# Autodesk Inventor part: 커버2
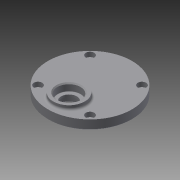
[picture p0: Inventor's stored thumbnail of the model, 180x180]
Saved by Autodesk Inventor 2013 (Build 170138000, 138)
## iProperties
Created: 2015-07
Part Number: 커버2
Material: 일반
Document SubType Name: Modeling
Designer: user
Density: 1 g/cm^3
Author: user
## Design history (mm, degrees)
sketch "스케치1"
  geometry: C1 r 40 at (0, 0); 1 further point
  constraints: 1 centre point, 1 coincident
  dimensions: "d0" = 80 diameter of C1
extrude "돌출1" new body sketch "스케치1" distance "d1" = 9; taper "d2" = 0 deg
sketch "스케치2"
  geometry: L1 (0, 0)-(0, 11); L2 (0, 0)-(0, -20); C1 r 40 at (0, 0) reference; C2 r 14 at (0, 11); C3 r 14 at (0, -20)
  constraints: 4 end point, 2 centre point, 2 coincident, 1 collinear, 1 vertical
  dimensions: "d3" = 11 distance of L1.start L1.end; "d4" = 20 distance of L1.start L2.end; "d5" = 28 diameter of C2; "d6" = 28 diameter of C3
extrude "돌출2" join sketch "스케치2" distance "d7" = 3; taper "d8" = 0 deg
sketch "스케치3"
  geometry: L1 (0, 0)-(0, -20); C1 r 40 at (0, 0) reference; C2 r 15 at (0, -20)
  constraints: 2 end point, 1 centre point, 1 coincident, 1 vertical
  dimensions: "d9" = 20 distance of L1.start L1.end; "d11" = 30 diameter of C2
extrude "돌출3" join sketch "스케치3" distance "d12" = 4; taper "d13" = 0 deg
fillet "모깎기1" dims "d14" = 2
chamfer "모따기1" distance "d15" = 1; stored, may be unused: second distance "d16" = 2, angle "d17" = 45 deg
hole "구멍1" diameter "d20" = 15; stored, may be unused: countersink angle "d24" = 90 deg, drill point angle "d26" = 0 deg; dims "d18" = 10, "d19" = 10, "d21" = 6, "d22" = 22, "d23" = 7, "d25" = 10
hole "구멍2" diameter "d29" = 22; stored, may be unused: countersink angle "d33" = 90 deg, drill point angle "d35" = 0 deg; dims "d27" = 10, "d28" = 10, "d30" = 6, "d31" = 22, "d32" = 7, "d34" = 7
hole "구멍3" diameter "d38" = 18; stored, may be unused: countersink angle "d42" = 90 deg, drill point angle "d44" = 0 deg; dims "d36" = 10, "d37" = 10, "d39" = 6, "d40" = 22, "d41" = 7, "d43" = 8
chamfer "모따기2" distance "d45" = 1; stored, may be unused: second distance "d46" = 2, angle "d47" = 45 deg
fillet "모깎기2" dims "d48" = 0.3
fillet "모깎기3" dims "d49" = 2
sketch "스케치4" dims "d50" = 70
  geometry: L1 (0, 0)-(24.749, 24.749); L2 (0, 0)-(35, 0); C1 r 40 at (0, 0) reference
  constraints: 4 end point, 1 coincident, 1 equal length, 1 horizontal, 3 other
  dimensions: "d51" = 45 deg angle of L2 L1
hole "구멍4" sketch "스케치4" at (24.749, 24.749) diameter "d52" = 4.5; stored, may be unused: countersink angle "d56" = 90 deg, drill point angle "d58" = 0 deg; dims "d53" = 6, "d54" = 8, "d55" = 4.4, "d57" = 10
node "솔리드1"
pattern_circular "원형 패턴1" dims angle "d60" = 360 deg
